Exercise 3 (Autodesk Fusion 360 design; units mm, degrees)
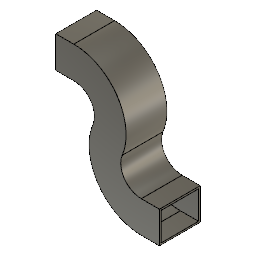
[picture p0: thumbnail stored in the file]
sketch "Sketch1" plane through (0, 0, 0) normal (0, 1, 0) x axis (1, 0, 0)
  line L1 (20, 0) -> (0, 0)
  line L2 (114.162, 110) -> (94.162, 110)
  arc A1 centre (20, 40) radius 40 clockwise from (57.081, 55) to (20, 0)
  arc A2 centre (94.162, 70) radius 40 clockwise from (57.081, 55) to (94.162, 110)
  point P1 (0, 0)
  point P2 (0, 0)
  point P3 (20, 0)
  point P6 (94.162, 110)
  point P8 (114.162, 110)
  coincident P1 P2
  horizontal L1
  tangent L1 A1
  horizontal L2
  tangent A1 A2
  tangent A2 L2
  dimension "d3" distance P2 P3 = 20
  dimension "d4" radius A1 = 40
  dimension "d5" radius A2 = 40
  dimension "d6" distance P6 P8 = 20
  dimension "d7" distance L1 L2 = 110
sketch "Sketch2" plane through (0, 0, 0) normal (1, 0, 0) x axis (0, 1, 0)
  line L1 (-22.5, 17.5) -> (22.5, 17.5)
  line L2 (-22.5, -17.5) -> (-22.5, 17.5)
  line L3 (22.5, -17.5) -> (-22.5, -17.5)
  line L4 (22.5, 17.5) -> (22.5, -17.5)
  line L5 (-22.5, -17.5) -> (22.5, 17.5)
  line L6 (22.5, -17.5) -> (-22.5, 17.5)
  line L7 (20.5, -15.5) -> (-20.5, -15.5)
  line L8 (20.5, 15.5) -> (20.5, -15.5)
  line L9 (-20.5, 15.5) -> (20.5, 15.5)
  line L10 (-20.5, -15.5) -> (-20.5, 15.5)
  point P6 (0, 0)
  point P1 (0, 0)
  point P2 (22.5, 17.5)
  point P3 (-22.5, 17.5)
  point P5 (22.5, -17.5)
  horizontal L1
  perpendicular L1 L2
  parallel L1 L3
  parallel L2 L4
  coincident L5 P6
  coincident L6 P6
  coincident P1 P6
  dimension "d8" distance P2 P3 = 45
  dimension "d9" distance P2 P5 = 35
  dimension "d10" = -2
sweep "Sweep1" sketch "Sketch2" TwistAngle 0 TaperAngle 0
sketch "Sketch3" plane through (114.162, 0, 0) normal (1, 0, 0) x axis (0, 1, 0)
